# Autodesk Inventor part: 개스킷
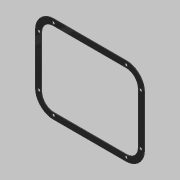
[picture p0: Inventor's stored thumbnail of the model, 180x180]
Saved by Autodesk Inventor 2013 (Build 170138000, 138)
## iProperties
Created: 2020-03
Part Number: 개스킷
Material: 고무
Document SubType Name: Modeling
Designer: mduedu
Density: 1 g/cm^3
Author: mduedu
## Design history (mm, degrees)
sketch "스케치1"
  geometry: L1 (-60, 72)-(60, 72); L2 (90, 42)-(90, -42); L3 (60, -72)-(-60, -72); L4 (-90, -42)-(-90, 42); L5 (60, 62)-(-60, 62); L6 (-80, 42)-(-80, -42); L7 (-60, -62)-(60, -62); L8 (80, -42)-(80, 42); A1 r 30 centre (-60, 42) between (-60, 72) and (-90, 42); A2 r 30 centre (60, 42) between (90, 42) and (60, 72); A3 r 30 centre (60, -42) between (60, -72) and (90, -42); A4 r 30 centre (-60, -42) between (-90, -42) and (-60, -72); A5 r 20 centre (-60, 42) between (-60, 62) and (-80, 42); A6 r 20 centre (-60, -42) between (-80, -42) and (-60, -62); A7 r 20 centre (60, -42) between (60, -62) and (80, -42); A8 r 20 centre (60, 42) between (80, 42) and (60, 62); 1 further point
  constraints: 16 end point, 16 point on circle, 8 centre point, 8 tangent, 4 parallel, 3 equal radius, 2 perpendicular, 1 horizontal, 7 other
  dimensions: "d0" = 180 distance between parallel lines of L2 L4; "d2" = 30 radius of A1; "d3" = 90 distance from line of point (0, 0) L4; "d4" = 72 distance from line of point (0, 0) L1; "d5" = 144 distance between parallel lines of L3 L1; "d6" = 10 distance between parallel lines of L5 L1
extrude "돌출1" new body sketch "스케치1" distance "d7" = 1; taper "d8" = 0 deg
sketch "스케치2"
  geometry: L1 (80, 42)-(80, -42) reference; L2 (60, -62)-(-60, -62) reference; L3 (-80, -42)-(-80, 42) reference; L4 (-60, 62)-(60, 62) reference; L5 (60, 72)-(-60, 72) reference; L6 (-90, 42)-(-90, -42) reference; L7 (-60, -72)-(60, -72) reference; L8 (90, -42)-(90, 42) reference; L9 (84, 42)-(84, -42); L10 (60, -66)-(-60, -66); L11 (-84, -42)-(-84, 42); L12 (-60, 66)-(60, 66); A1 r 20 centre (60, 42) between (80, 42) and (60, 62) reference; A2 r 20 centre (60, -42) between (60, -62) and (80, -42) reference; A3 r 20 centre (-60, -42) between (-80, -42) and (-60, -62) reference; A4 r 20 centre (-60, 42) between (-60, 62) and (-80, 42) reference; A5 r 30 centre (-60, 42) between (-60, 72) and (-90, 42) reference; A6 r 30 centre (-60, -42) between (-90, -42) and (-60, -72) reference; A7 r 30 centre (60, -42) between (60, -72) and (90, -42) reference; A8 r 30 centre (60, 42) between (90, 42) and (60, 72) reference; A9 r 24 centre (60, 42) between (84, 42) and (60, 66); A10 r 24 centre (60, -42) between (60, -66) and (84, -42); A11 r 24 centre (-60, -42) between (-84, -42) and (-60, -66); A12 r 24 centre (-60, 42) between (-60, 66) and (-84, 42); 9 further points
  constraints: 8 coincident, 8 end point, 8 point on circle, 4 centre point, 7 other
  dimensions: "d17" = 6 distance between parallel lines of L12 L5
hole "구멍1" sketch "스케치2" at (-60, 66), (-84, 42), (-84, -42), (-60, -66), (60, -66), (84, -42), (84, 42), (60, 66) diameter "d10" = 4.5; stored, may be unused: countersink angle "d14" = 90 deg, drill point angle "d16" = 118 deg; dims "d11" = 6, "d12" = 4, "d13" = 2, "d15" = 8
node "솔리드1"
node "투영된 루프1"
